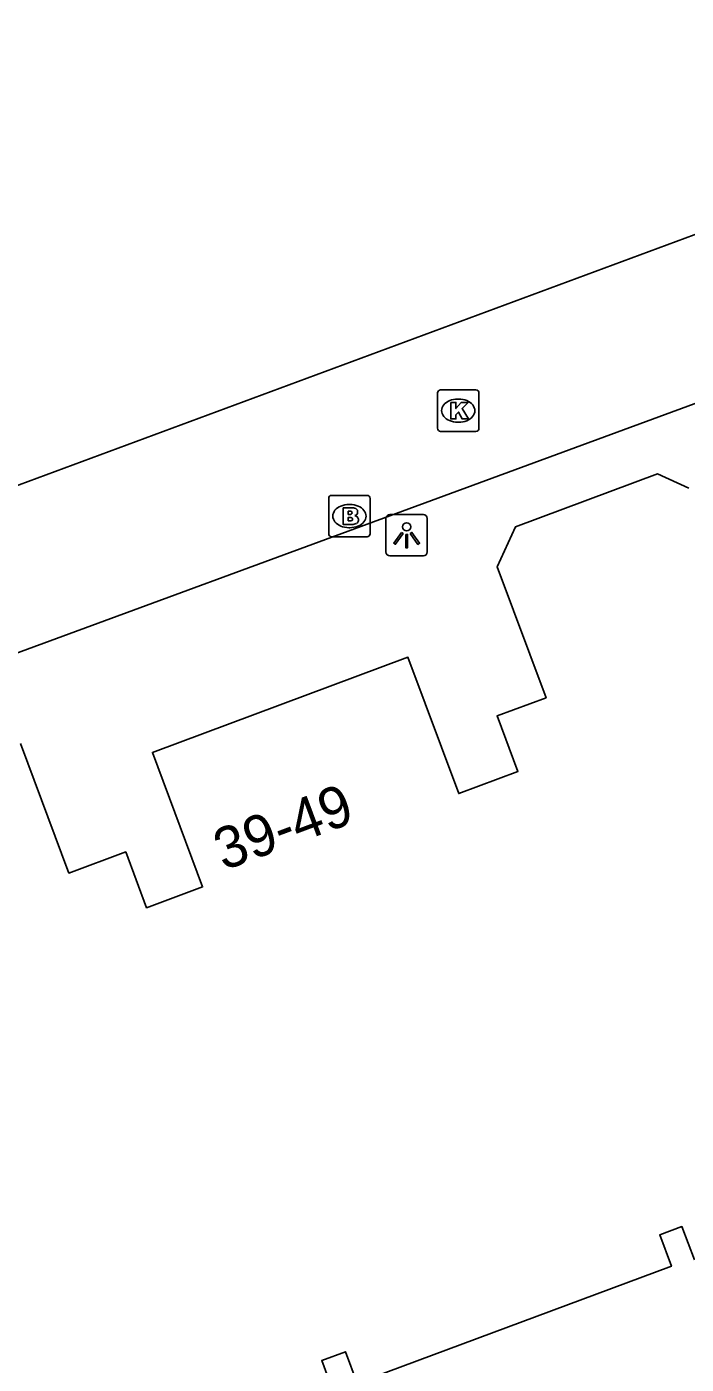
# Model space of a CAD drawing. Extents: x 160806 to 161707, y 383697 to 384148.
# Drawn here: x 161004.31 to 161020.22, y 383872.31 to 383904.59 of the extents above; entities that cross this region are included whole.
import ezdxf

# ---------------------------------------------------------------- set-up
doc = ezdxf.new("R2010")
doc.units = 0
for name, color, linetype in [('IMGEO_Brandkraan', 7, 'Continuous'), ('IMGEO_Kolk', 7, 'Continuous'), ('IMGEO_Lichtpunt', 7, 'Continuous'), ('IMGEO_Pand', 7, 'Continuous'), ('IMGEO_Pand_nummerreeks', 7, 'Continuous'), ('IMGEO_Rijbaan_lokaal_open', 7, 'Continuous')]:
    doc.layers.add(name, color=color, linetype=linetype)

msp = doc.modelspace()

# ---------------------------------------------------------------- linework, layer by layer
at = {"layer": 'IMGEO_Brandkraan'}
for p, q in [((161011.595, 383892.353), (161011.595, 383893.205)), ((161011.67, 383893.279), (161012.522, 383893.279)), ((161012.083, 383893.059), (161012.108, 383893.059)), ((161012.596, 383893.205), (161012.596, 383892.353)), ((161012.106, 383892.499), (161012.081, 383892.499)), ((161012.522, 383892.279), (161011.67, 383892.279))]:
    msp.add_line(p, q, dxfattribs=at)
for points in [[(161011.595, 383892.353), (161011.595, 383893.205)], [(161011.67, 383893.279), (161012.522, 383893.279)], [(161012.596, 383893.205), (161012.596, 383892.353)], [(161011.943, 383892.979), (161011.943, 383892.579), (161012.156, 383892.579)], [(161012.174, 383892.979), (161011.943, 383892.979)], [(161012.122, 383892.898), (161012.068, 383892.898), (161012.068, 383892.822)], [(161012.068, 383892.822), (161012.121, 383892.822)], [(161012.13, 383892.746), (161012.068, 383892.746), (161012.068, 383892.665)], [(161012.068, 383892.665), (161012.13, 383892.665)], [(161012.522, 383892.279), (161011.67, 383892.279)]]:
    msp.add_lwpolyline(points, dxfattribs=at)
for centre, radius, start, end in [((161011.672, 383893.203), 0.0765, 91.552, 178.448), ((161011.672, 383893.203), 0.0765, 91.552, 178.448), ((161012.52, 383893.203), 0.0765, 1.552, 88.448), ((161012.52, 383893.203), 0.0765, 1.552, 88.448), ((161012.123, 383892.86), 0.0379, 267.8285, 90.9355), ((161012.131, 383892.705), 0.0404, 269.8759, 90.5077), ((161012.178, 383892.834), 0.145, 59.4692, 91.5367), ((161012.203, 383892.881), 0.0922, 285.5137, 58.1501), ((161012.208, 383892.689), 0.105, 301.3115, 78.989), ((161012.162, 383892.83), 0.251, 268.6676, 293.5347), ((161011.672, 383892.355), 0.0765, 181.552, 268.448), ((161011.672, 383892.355), 0.0765, 181.552, 268.448), ((161012.52, 383892.355), 0.0765, 271.552, 358.448), ((161012.52, 383892.355), 0.0765, 271.552, 358.448)]:
    msp.add_arc(centre, radius, start, end, dxfattribs=at)
for centre, major_axis, ratio, start_param, end_param in [((161012.082, 383892.779), (-0.387, 0.002), 0.722429, 4.712389, 7.853982), ((161012.107, 383892.779), (-0.39, 0.002), 0.717154, 1.570796, 4.712389)]:
    msp.add_ellipse(centre, major_axis=major_axis, ratio=ratio, start_param=start_param, end_param=end_param, dxfattribs=at)
at = {"layer": 'IMGEO_Kolk'}
for p, q in [((161014.219, 383894.899), (161014.219, 383895.751)), ((161014.294, 383895.825), (161015.146, 383895.825)), ((161014.707, 383895.605), (161014.732, 383895.605)), ((161015.22, 383895.751), (161015.22, 383894.899)), ((161014.73, 383895.045), (161014.705, 383895.045)), ((161015.146, 383894.825), (161014.294, 383894.825))]:
    msp.add_line(p, q, dxfattribs=at)
for points in [[(161014.219, 383894.899), (161014.219, 383895.751)], [(161014.294, 383895.825), (161015.146, 383895.825)], [(161015.22, 383895.751), (161015.22, 383894.899)], [(161014.54, 383895.525), (161014.663, 383895.525), (161014.663, 383895.374), (161014.793, 383895.525), (161014.957, 383895.525), (161014.811, 383895.374), (161014.964, 383895.125), (161014.812, 383895.125), (161014.727, 383895.289), (161014.663, 383895.222), (161014.663, 383895.125), (161014.54, 383895.125), (161014.54, 383895.525)], [(161015.146, 383894.825), (161014.294, 383894.825)]]:
    msp.add_lwpolyline(points, dxfattribs=at)
for centre, start, end in [((161014.296, 383895.749), 91.552, 178.448), ((161014.296, 383895.749), 91.552, 178.448), ((161015.144, 383895.749), 1.552, 88.448), ((161015.144, 383895.749), 1.552, 88.448), ((161014.296, 383894.901), 181.552, 268.448), ((161014.296, 383894.901), 181.552, 268.448), ((161015.144, 383894.901), 271.552, 358.448), ((161015.144, 383894.901), 271.552, 358.448)]:
    msp.add_arc(centre, 0.0765, start, end, dxfattribs=at)
for centre, major_axis, ratio, start_param, end_param in [((161014.706, 383895.325), (-0.387, 0.002), 0.722429, 4.712389, 7.853982), ((161014.731, 383895.325), (-0.39, 0.002), 0.717154, 1.570796, 4.712389)]:
    msp.add_ellipse(centre, major_axis=major_axis, ratio=ratio, start_param=start_param, end_param=end_param, dxfattribs=at)
at = {"layer": 'IMGEO_Lichtpunt'}
for p, q in [((161012.977, 383892.722), (161012.977, 383891.915)), ((161012.977, 383892.722), (161012.977, 383891.915)), ((161013.879, 383892.817), (161013.071, 383892.817)), ((161013.879, 383892.817), (161013.071, 383892.817)), ((161013.973, 383891.915), (161013.973, 383892.722)), ((161013.973, 383891.915), (161013.973, 383892.722)), ((161013.071, 383891.821), (161013.879, 383891.821)), ((161013.071, 383891.821), (161013.879, 383891.821))]:
    msp.add_line(p, q, dxfattribs=at)
for points in [[(161013.351, 383892.386), (161013.39, 383892.358), (161013.202, 383892.096), (161013.164, 383892.123), (161013.351, 383892.386)], [(161013.563, 383892.358), (161013.601, 383892.385), (161013.788, 383892.123), (161013.749, 383892.095), (161013.563, 383892.358)], [(161013.453, 383892.338), (161013.5, 383892.338), (161013.5, 383892.016), (161013.453, 383892.016), (161013.453, 383892.338)]]:
    msp.add_lwpolyline(points, dxfattribs=at)
msp.add_circle((161013.476, 383892.52), 0.0994, dxfattribs=at)
for centre, start, end in [((161013.071, 383892.722), 90, 180), ((161013.071, 383892.722), 90, 180), ((161013.879, 383892.722), 0, 90), ((161013.879, 383892.722), 0, 90), ((161013.071, 383891.915), 180, 270), ((161013.071, 383891.915), 180, 270), ((161013.879, 383891.915), 270, 0), ((161013.879, 383891.915), 270, 360)]:
    msp.add_arc(centre, 0.0946, start, end, dxfattribs=at)
at = {"layer": 'IMGEO_Pand'}
for points in [[(161020.283, 383893.45), (161019.525, 383893.797), (161016.103, 383892.522), (161015.661, 383891.555), (161016.839, 383888.395), (161015.659, 383887.955), (161016.159, 383886.612), (161014.732, 383886.081), (161013.506, 383889.371), (161007.345, 383887.075), (161008.555, 383883.828), (161007.202, 383883.324), (161006.699, 383884.673), (161005.328, 383884.163), (161004.162, 383887.291)], [(161011.721, 383871.611), (161011.429, 383872.394), (161012.003, 383872.607), (161012.285, 383871.849), (161019.861, 383874.671), (161019.579, 383875.428), (161020.116, 383875.629), (161020.415, 383874.828)]]:
    msp.add_lwpolyline(points, dxfattribs=at)
at = {"layer": 'IMGEO_Rijbaan_lokaal_open'}
for points in [[(161034.783, 383900.781), (161000, 383887.972), (160991.432, 383884.817), (160990.275, 383885.032), (160986.341, 383885.715), (160984.869, 383885.974), (160968.05, 383879.828), (160959.806, 383902.516), (160960.137, 383903.811), (160950.161, 383931.007)], [(160974.531, 383886.634), (160982.677, 383889.672), (160990.074, 383888.326), (161000, 383892.005), (161033.437, 383904.394)]]:
    msp.add_lwpolyline(points, dxfattribs=at)

# ---------------------------------------------------------------- texts
at = {"layer": 'IMGEO_Pand_nummerreeks'}
msp.add_text('39-49', height=1, rotation=20.4374, dxfattribs=at).set_placement((161009.063, 383884.215))

doc.saveas('drawing.dxf')
